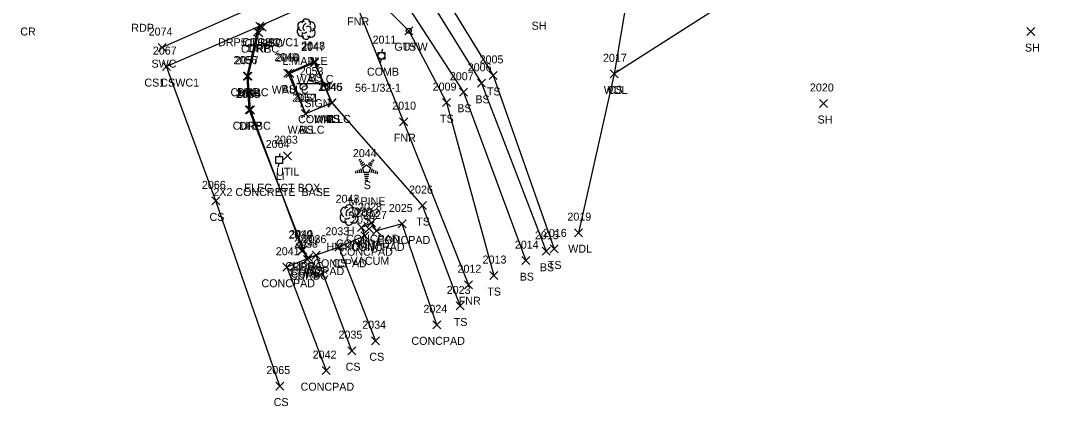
# Model space of a CAD drawing. Extents: x 1477930 to 1480780, y 774090 to 784647.
# Drawn here: x 1478653 to 1478912.6, y 774249.4 to 774345.7 of the extents above; entities that cross this region are included whole.
import ezdxf

# ---------------------------------------------------------------- set-up
doc = ezdxf.new("R2010")
doc.units = 0
for name, color, linetype in [('L_A', 7, 'Continuous'), ('L_C', 7, 'Continuous'), ('L_I', 7, 'Continuous'), ('L_TIC', 7, 'Continuous'), ('LAWA', 7, 'Continuous'), ('LELB', 7, 'Continuous'), ('LFNC', 7, 'Continuous'), ('LS', 7, 'Continuous'), ('LTC', 7, 'Continuous'), ('LTD', 7, 'Continuous'), ('LW', 7, 'Continuous'), ('P_A', 7, 'Continuous'), ('P_I', 7, 'Continuous'), ('P_TIC', 7, 'Continuous'), ('R_A', 7, 'Continuous'), ('R_I', 7, 'Continuous'), ('R_TIC', 7, 'Continuous'), ('RC', 7, 'Continuous'), ('RDP', 7, 'Continuous'), ('RSW', 7, 'Continuous'), ('S_A', 7, 'Continuous'), ('S_C', 7, 'Continuous'), ('S_I', 7, 'Continuous'), ('SSGN', 7, 'Continuous'), ('U_A', 7, 'Continuous'), ('U_C', 7, 'Continuous'), ('U_I', 7, 'Continuous'), ('UDEFAULT', 7, 'Continuous'), ('ULP', 7, 'Continuous'), ('UP', 7, 'Continuous'), ('UPGW', 7, 'Continuous')]:
    doc.layers.add(name, color=color, linetype=linetype)

msp = doc.modelspace()

# ---------------------------------------------------------------- linework, layer by layer
at = {"layer": 'L_TIC'}
for points in [[(1478748.89, 774342.18), (1478750.89, 774344.18)], [(1478750.89, 774342.18), (1478748.89, 774344.18)], [(1478904.33, 774341.96), (1478906.33, 774343.96)], [(1478906.33, 774341.96), (1478904.33, 774343.96)], [(1478688.34, 774333.22), (1478690.34, 774335.22)], [(1478690.34, 774333.22), (1478688.34, 774335.22)], [(1478725.32, 774334.13), (1478727.32, 774336.13)], [(1478727.32, 774334.13), (1478725.32, 774336.13)], [(1478725.36, 774334.46), (1478727.36, 774336.46)], [(1478727.36, 774334.46), (1478725.36, 774336.46)], [(1478718.65, 774331.61), (1478720.65, 774333.61)], [(1478720.65, 774331.61), (1478718.65, 774333.61)], [(1478719.13, 774331.46), (1478721.13, 774333.46)], [(1478721.13, 774331.46), (1478719.13, 774333.46)], [(1478770, 774331.01), (1478772, 774333.01)], [(1478772, 774331.01), (1478770, 774333.01)], [(1478800.18, 774331.41), (1478802.18, 774333.41)], [(1478802.18, 774331.41), (1478800.18, 774333.41)], [(1478800.18, 774331.41), (1478802.18, 774333.41)], [(1478802.18, 774331.41), (1478800.18, 774333.41)], [(1478767.09, 774329.04), (1478769.09, 774331.04)], [(1478769.09, 774329.04), (1478767.09, 774331.04)], [(1478758.29, 774324.22), (1478760.29, 774326.22)], [(1478760.29, 774324.22), (1478758.29, 774326.22)], [(1478762.57, 774326.81), (1478764.57, 774328.81)], [(1478764.57, 774326.81), (1478762.57, 774328.81)], [(1478729.67, 774324.14), (1478731.67, 774326.14)], [(1478731.67, 774324.14), (1478729.67, 774326.14)], [(1478729.67, 774324.14), (1478731.67, 774326.14)], [(1478731.67, 774324.14), (1478729.67, 774326.14)], [(1478729.78, 774324.15), (1478731.78, 774326.15)], [(1478731.78, 774324.15), (1478729.78, 774326.15)], [(1478729.78, 774324.15), (1478731.78, 774326.15)], [(1478731.78, 774324.15), (1478729.78, 774326.15)], [(1478729.78, 774324.15), (1478731.78, 774326.15)], [(1478731.78, 774324.15), (1478729.78, 774326.15)], [(1478852.53, 774324), (1478854.53, 774326)], [(1478854.53, 774324), (1478852.53, 774326)], [(1478723.08, 774321.46), (1478725.08, 774323.46)], [(1478725.08, 774321.46), (1478723.08, 774323.46)], [(1478723.08, 774321.46), (1478725.08, 774323.46)], [(1478725.08, 774321.46), (1478723.08, 774323.46)], [(1478723.09, 774321.43), (1478725.09, 774323.43)], [(1478725.09, 774321.43), (1478723.09, 774323.43)], [(1478723.09, 774321.43), (1478725.09, 774323.43)], [(1478725.09, 774321.43), (1478723.09, 774323.43)], [(1478747.61, 774319.46), (1478749.61, 774321.46)], [(1478749.61, 774319.46), (1478747.61, 774321.46)], [(1478700.65, 774299.67), (1478702.65, 774301.67)], [(1478702.65, 774299.67), (1478700.65, 774301.67)], [(1478752.35, 774298.5), (1478754.35, 774300.5)], [(1478754.35, 774298.5), (1478752.35, 774300.5)], [(1478739.57, 774294.21), (1478741.57, 774296.21)], [(1478741.57, 774294.21), (1478739.57, 774296.21)], [(1478747.24, 774293.9), (1478749.24, 774295.9)], [(1478749.24, 774293.9), (1478747.24, 774295.9)], [(1478737.07, 774293.02), (1478739.07, 774295.02)], [(1478739.07, 774293.02), (1478737.07, 774295.02)], [(1478737.89, 774290.97), (1478739.89, 774292.97)], [(1478739.89, 774290.97), (1478737.89, 774292.97)], [(1478738.95, 774292.7), (1478740.95, 774294.7)], [(1478740.95, 774292.7), (1478738.95, 774294.7)], [(1478740.83, 774292.18), (1478742.83, 774294.18)], [(1478742.83, 774292.18), (1478740.83, 774294.18)], [(1478791.3, 774291.73), (1478793.3, 774293.73)], [(1478793.3, 774291.73), (1478791.3, 774293.73)], [(1478731.39, 774288.09), (1478733.39, 774290.09)], [(1478733.39, 774288.09), (1478731.39, 774290.09)], [(1478731.39, 774288.09), (1478733.39, 774290.09)], [(1478733.39, 774288.09), (1478731.39, 774290.09)], [(1478725.74, 774286.12), (1478727.74, 774288.12)], [(1478727.74, 774286.12), (1478725.74, 774288.12)], [(1478725.74, 774286.12), (1478727.74, 774288.12)], [(1478727.74, 774286.12), (1478725.74, 774288.12)], [(1478783.18, 774287.09), (1478785.18, 774289.09)], [(1478785.18, 774287.09), (1478783.18, 774289.09)], [(1478785.22, 774287.67), (1478787.22, 774289.67)], [(1478787.22, 774287.67), (1478785.22, 774289.67)], [(1478718.43, 774283.09), (1478720.43, 774285.09)], [(1478720.43, 774283.09), (1478718.43, 774285.09)], [(1478778.16, 774284.74), (1478780.16, 774286.74)], [(1478780.16, 774284.74), (1478778.16, 774286.74)], [(1478770.1, 774281.02), (1478772.1, 774283.02)], [(1478772.1, 774281.02), (1478770.1, 774283.02)], [(1478763.83, 774278.72), (1478765.83, 774280.72)], [(1478765.83, 774278.72), (1478763.83, 774280.72)], [(1478761.71, 774273.42), (1478763.71, 774275.42)], [(1478763.71, 774273.42), (1478761.71, 774275.42)], [(1478755.89, 774268.71), (1478757.89, 774270.71)], [(1478757.89, 774268.71), (1478755.89, 774270.71)], [(1478740.6, 774264.73), (1478742.6, 774266.73)], [(1478742.6, 774264.73), (1478740.6, 774266.73)], [(1478734.67, 774262.25), (1478736.67, 774264.25)], [(1478736.67, 774262.25), (1478734.67, 774264.25)], [(1478728.22, 774257.26), (1478730.22, 774259.26)], [(1478730.22, 774257.26), (1478728.22, 774259.26)], [(1478716.68, 774253.41), (1478718.68, 774255.41)], [(1478718.68, 774253.41), (1478716.68, 774255.41)]]:
    msp.add_lwpolyline(points, dxfattribs=at)
at = {"layer": 'LAWA'}
msp.add_lwpolyline([(1479011.38, 774343.55), (1478995.1, 774366.59), (1478968.24, 774384.07), (1478947.58, 774395.67), (1478961.25, 774413.39), (1478952.73, 774420.76), (1478901.61, 774417.12), (1478856.8, 774391.87), (1478808.81, 774377.19), (1478801.18, 774332.41), (1478792.3, 774292.73)], dxfattribs=at)
at = {"layer": 'LELB'}
for points in [[(1478934.45, 774450.58), (1478925.02, 774444.04), (1478895.86, 774426.81), (1478850.02, 774405.81), (1478804.52, 774385.73), (1478757.11, 774369.6), (1478745.11, 774364.76), (1478741.82, 774359.99), (1478746.47, 774354.13), (1478763.57, 774327.81), (1478779.16, 774285.74)], [(1478959.46, 774383.59), (1478932.04, 774383.18), (1478897.67, 774379.29), (1478866.23, 774373.98), (1478801.18, 774332.41)], [(1478757.11, 774369.6), (1478758.28, 774367.33), (1478749.03, 774360.76), (1478768.09, 774330.04), (1478784.18, 774288.09)], [(1478758.28, 774367.33), (1478753.39, 774360.66), (1478771, 774332.01), (1478786.22, 774288.67)], [(1478734.59, 774354.16), (1478739.86, 774353.19), (1478749.89, 774343.18), (1478759.29, 774325.22), (1478771.1, 774282.02)], [(1478717.68, 774254.41), (1478701.65, 774300.67), (1478689.34, 774334.22)], [(1478730.78, 774325.15), (1478726.36, 774335.46), (1478719.65, 774332.61), (1478724.09, 774322.43)], [(1478730.78, 774325.15), (1478724.09, 774322.43)], [(1478762.71, 774274.42), (1478753.35, 774299.5), (1478730.78, 774325.15)], [(1478732.39, 774289.09), (1478741.6, 774265.73)], [(1478735.67, 774263.25), (1478726.74, 774287.12)]]:
    msp.add_lwpolyline(points, dxfattribs=at)
at = {"layer": 'LFNC'}
msp.add_lwpolyline([(1478736.95, 774349.5), (1478748.61, 774320.46), (1478764.83, 774279.72)], dxfattribs=at)
at = {"layer": 'LS'}
msp.add_lwpolyline([(1478756.89, 774269.71), (1478748.24, 774294.9), (1478741.83, 774293.18), (1478740.57, 774295.21), (1478738.07, 774294.02), (1478738.89, 774291.97), (1478732.39, 774289.09), (1478726.74, 774287.12), (1478719.43, 774284.09), (1478729.22, 774258.26)], dxfattribs=at)
at = {"layer": 'LTC'}
for p, q in [((1478737.44, 774310.81), (1478737.8, 774311.07)), ((1478737.65, 774310.35), (1478738.18, 774310.73)), ((1478740.47, 774310.71), (1478741.02, 774310.31)), ((1478740.84, 774311.05), (1478741.26, 774310.75)), ((1478736.48, 774308.09), (1478736.63, 774307.62)), ((1478736.93, 774308.31), (1478737.14, 774307.66)), ((1478737.39, 774308.53), (1478737.66, 774307.69)), ((1478737.84, 774308.74), (1478738.17, 774307.72)), ((1478737.86, 774309.88), (1478738.57, 774310.39)), ((1478738.07, 774309.42), (1478738.95, 774310.05)), ((1478738.3, 774308.96), (1478739.31, 774309.7)), ((1478738.3, 774308.96), (1478738.68, 774307.77)), ((1478739.31, 774309.7), (1478740.3, 774308.97)), ((1478739.73, 774310.01), (1478740.54, 774309.42)), ((1478740.3, 774308.97), (1478739.91, 774307.77)), ((1478740.1, 774310.36), (1478740.78, 774309.86)), ((1478740.74, 774308.7), (1478740.4, 774307.66)), ((1478741.19, 774308.45), (1478740.9, 774307.56)), ((1478741.63, 774308.2), (1478741.39, 774307.47)), ((1478739.91, 774307.77), (1478738.68, 774307.77)), ((1478739.88, 774307.27), (1478738.73, 774307.27)), ((1478739.79, 774306.77), (1478738.8, 774306.77)), ((1478739.71, 774306.27), (1478738.88, 774306.27)), ((1478739.62, 774305.77), (1478738.95, 774305.77)), ((1478742.08, 774307.95), (1478741.89, 774307.37))]:
    msp.add_line(p, q, dxfattribs=at)
at = {"layer": 'LTD'}
for p, q in [((1478724.21, 774343.63), (1478724.21, 774343.63)), ((1478724.21, 774343.63), (1478724.21, 774343.63)), ((1478734.94, 774297.2), (1478734.94, 774297.2)), ((1478734.94, 774297.2), (1478734.94, 774297.2))]:
    msp.add_line(p, q, dxfattribs=at)
for centre in [(1478724.26, 774345.06), (1478734.99, 774298.63)]:
    msp.add_arc(centre, 1.05, 335.5272, 180.9563, dxfattribs=at)
for centre, major_axis, ratio, start_param, end_param in [((1478723.42, 774344.29), (1.21, -0.51), 0.895232, 1.570796, 4.712389), ((1478724.01, 774344.09), (-0.208, -0.792), 0.645439, 3.141593, 6.283185), ((1478724.72, 774343.46), (-0.5, 0.667), 0.989748, 3.141593, 6.283185), ((1478725.26, 774344.21), (-1.14, -0.48), 0.949671, 1.570796, 4.712389), ((1478723.13, 774342.92), (0.58, -1.04), 0.959034, 3.141593, 6.283185), ((1478724.22, 774342.13), (0.26, 1.06), 0.942809, 1.570796, 4.712389), ((1478723.76, 774342.88), (-0.625, -0.083), 0.423636, 0, 3.141593), ((1478725.22, 774342.8), (-1.09, 0.79), 0.841452, 1.570796, 4.712389), ((1478734.15, 774297.87), (1.21, -0.51), 0.895232, 1.570796, 4.712389), ((1478734.74, 774297.66), (-0.208, -0.792), 0.645439, 3.141593, 6.283185), ((1478735.44, 774297.03), (-0.5, 0.667), 0.989748, 3.141593, 6.283185), ((1478735.99, 774297.78), (-1.14, -0.48), 0.949671, 1.570796, 4.712389), ((1478733.86, 774296.49), (0.58, -1.04), 0.959034, 3.141593, 6.283185), ((1478734.94, 774295.7), (0.26, 1.06), 0.942809, 1.570796, 4.712389), ((1478734.49, 774296.45), (-0.625, -0.083), 0.423636, 0, 3.141593), ((1478735.94, 774296.37), (-1.09, 0.79), 0.841452, 1.570796, 4.712389)]:
    msp.add_ellipse(centre, major_axis=major_axis, ratio=ratio, start_param=start_param, end_param=end_param, dxfattribs=at)
at = {"layer": 'LW'}
for points in [[(1478730.67, 774325.14), (1478726.32, 774335.13), (1478720.13, 774332.46), (1478724.08, 774322.46)], [(1478730.67, 774325.14), (1478724.08, 774322.46)]]:
    msp.add_lwpolyline(points, dxfattribs=at)
at = {"layer": 'P_TIC'}
for points in [[(1478722.17, 774287.23), (1478724.17, 774289.23)], [(1478724.17, 774287.23), (1478722.17, 774289.23)]]:
    msp.add_lwpolyline(points, dxfattribs=at)
at = {"layer": 'R_TIC'}
for points in [[(1478711.68, 774343.31), (1478713.68, 774345.31)], [(1478713.68, 774343.31), (1478711.68, 774345.31)], [(1478711.68, 774343.31), (1478713.68, 774345.31)], [(1478713.68, 774343.31), (1478711.68, 774345.31)], [(1478711.68, 774343.31), (1478713.68, 774345.31)], [(1478713.68, 774343.31), (1478711.68, 774345.31)], [(1478712.29, 774343.07), (1478714.29, 774345.07)], [(1478714.29, 774343.07), (1478712.29, 774345.07)], [(1478711.12, 774341.88), (1478713.12, 774343.88)], [(1478713.12, 774341.88), (1478711.12, 774343.88)], [(1478711.39, 774341.69), (1478713.39, 774343.69)], [(1478713.39, 774341.69), (1478711.39, 774343.69)], [(1478687.25, 774337.96), (1478689.25, 774339.96)], [(1478689.25, 774337.96), (1478687.25, 774339.96)], [(1478688.34, 774333.22), (1478690.34, 774335.22)], [(1478690.34, 774333.22), (1478688.34, 774335.22)], [(1478708.48, 774330.85), (1478710.48, 774332.85)], [(1478710.48, 774330.85), (1478708.48, 774332.85)], [(1478708.78, 774330.81), (1478710.78, 774332.81)], [(1478710.78, 774330.81), (1478708.78, 774332.81)], [(1478709.02, 774322.41), (1478711.02, 774324.41)], [(1478711.02, 774322.41), (1478709.02, 774324.41)], [(1478709.32, 774322.45), (1478711.32, 774324.45)], [(1478711.32, 774322.45), (1478709.32, 774324.45)], [(1478722.45, 774287.39), (1478724.45, 774289.39)], [(1478724.45, 774287.39), (1478722.45, 774289.39)], [(1478723.81, 774285.51), (1478725.81, 774287.51)], [(1478725.81, 774285.51), (1478723.81, 774287.51)], [(1478723.59, 774284.99), (1478725.59, 774286.99)], [(1478725.59, 774284.99), (1478723.59, 774286.99)], [(1478723.59, 774284.99), (1478725.59, 774286.99)], [(1478725.59, 774284.99), (1478723.59, 774286.99)]]:
    msp.add_lwpolyline(points, dxfattribs=at)
at = {"layer": 'RC'}
msp.add_lwpolyline([(1478724.81, 774286.51), (1478724.59, 774285.99), (1478723.45, 774288.39), (1478710.32, 774323.45), (1478709.78, 774331.81), (1478712.39, 774342.69), (1478712.68, 774344.31), (1478713.29, 774344.07)], dxfattribs=at)
at = {"layer": 'RDP'}
msp.add_lwpolyline([(1478724.59, 774285.99), (1478710.02, 774323.41), (1478709.48, 774331.85), (1478712.12, 774342.88), (1478712.68, 774344.31)], dxfattribs=at)
at = {"layer": 'RSW'}
for points in [[(1478732.52, 774358.51), (1478715.18, 774350.96), (1478688.25, 774338.96)], [(1478732.52, 774358.51), (1478734.59, 774354.16), (1478712.68, 774344.31), (1478689.34, 774334.22)]]:
    msp.add_lwpolyline(points, dxfattribs=at)
at = {"layer": 'SSGN'}
for p, q in [((1478721.95, 774330), (1478730.55, 774330)), ((1478725.97, 774329.09), (1478725.97, 774329.09))]:
    msp.add_line(p, q, dxfattribs=at)
for centre in [(1478723.61, 774329.16), (1478728.83, 774329.09)]:
    msp.add_circle(centre, 0.833, dxfattribs=at)
at = {"layer": 'UDEFAULT'}
for points in [[(1478718.6, 774310.96), (1478720.6, 774312.96)], [(1478720.6, 774310.96), (1478718.6, 774312.96)]]:
    msp.add_lwpolyline(points, dxfattribs=at)
at = {"layer": 'ULP'}
for p, q in [((1478716.7, 774310.05), (1478716.7, 774311.72)), ((1478716.7, 774311.72), (1478718.36, 774311.72)), ((1478717.7, 774312.55), (1478717.53, 774311.72)), ((1478717.53, 774310.88), (1478717.53, 774310.88)), ((1478718.36, 774311.72), (1478718.36, 774310.05)), ((1478718.36, 774310.05), (1478716.7, 774310.05)), ((1478717.28, 774309.22), (1478717.53, 774310.05))]:
    msp.add_line(p, q, dxfattribs=at)
at = {"layer": 'UP'}
for p, q in [((1478742.22, 774336.11), (1478742.22, 774337.78)), ((1478742.22, 774337.78), (1478743.89, 774337.78)), ((1478743.3, 774338.61), (1478743.05, 774337.78)), ((1478743.05, 774336.94), (1478743.05, 774336.94)), ((1478743.89, 774337.78), (1478743.89, 774336.11)), ((1478743.89, 774336.11), (1478742.22, 774336.11)), ((1478742.8, 774335.28), (1478743.05, 774336.11))]:
    msp.add_line(p, q, dxfattribs=at)
msp.add_circle((1478743.05, 774336.94), 0.833, dxfattribs=at)
at = {"layer": 'UPGW'}
for radius in [0.625, 0.0833]:
    msp.add_circle((1478749.89, 774343.18), radius, dxfattribs=at)

# ---------------------------------------------------------------- texts
at = {"layer": 'L_A'}
for s, p in [('FNR', (1478734.49, 774344.5)), ('SH', (1478780.57, 774343.43)), ('H', (1478723.65, 774338.63)), ('TS', (1478748.3, 774338.18)), ('SH', (1478903.82, 774337.96)), ('WALLC', (1478721.86, 774330.13)), ('BS', (1478724.8, 774330.46)), ('CS', (1478687.78, 774329.22)), ('WALLC', (1478715.66, 774327.46)), ('BS', (1478718.1, 774327.61)), ('TS', (1478769.41, 774327.01)), ('WDL', (1478798.6, 774327.41)), ('CS', (1478799.62, 774327.41)), ('BS', (1478766.53, 774325.04)), ('BS', (1478762.01, 774322.81)), ('WALLC', (1478726.21, 774320.14)), ('WALLC', (1478726.21, 774320.14)), ('TS', (1478729.19, 774320.15)), ('BS', (1478729.22, 774320.15)), ('BS', (1478729.22, 774320.15)), ('TS', (1478757.7, 774320.22)), ('SH', (1478852.02, 774320)), ('WALLC', (1478719.62, 774317.46)), ('WALLC', (1478719.62, 774317.46)), ('BS', (1478722.53, 774317.43)), ('BS', (1478722.53, 774317.43)), ('FNR', (1478746.15, 774315.46)), ('S', (1478738.63, 774303.6)), ('CS', (1478700.1, 774295.67)), ('TS', (1478751.76, 774294.5)), ('H', (1478734.38, 774292.2)), ('CONCPAD', (1478731.71, 774289.02)), ('CONCPAD', (1478734.22, 774290.21)), ('CONCPAD', (1478735.47, 774288.18)), ('MMF', (1478737.24, 774288.7)), ('CONCPAD', (1478741.89, 774289.9)), ('CONCPAD', (1478732.53, 774286.97)), ('WDL', (1478789.72, 774287.73)), ('CONCPAD', (1478726.03, 774284.09)), ('CS', (1478730.83, 774284.09)), ('BS', (1478782.62, 774283.09)), ('TS', (1478784.63, 774283.67)), ('CONCPAD', (1478720.39, 774282.12)), ('CS', (1478725.18, 774282.12)), ('BS', (1478777.6, 774280.74)), ('CONCPAD', (1478713.08, 774279.09)), ('TS', (1478769.51, 774277.02)), ('FNR', (1478762.37, 774274.72)), ('TS', (1478761.12, 774269.42)), ('CONCPAD', (1478750.54, 774264.71)), ('CS', (1478740.04, 774260.73)), ('CS', (1478734.11, 774258.25)), ('CONCPAD', (1478722.86, 774253.26)), ('CS', (1478716.13, 774249.41))]:
    msp.add_text(s, height=2, dxfattribs=at).set_placement(p)
at = {"layer": 'L_C'}
for s, p in [('L.MAPLE', (1478718.33, 774334.63)), ('M.PINE', (1478734.85, 774299.6)), ('HICKORY', (1478729.32, 774288.2)), ('VACUM', (1478735.35, 774284.7))]:
    msp.add_text(s, height=2, dxfattribs=at).set_placement(p)
at = {"layer": 'L_I'}
for s, p in [('2067', (1478685.95, 774337.22)), ('2047', (1478722.99, 774338.13)), ('2048', (1478723.02, 774338.46)), ('2049', (1478716.31, 774335.61)), ('2050', (1478716.7, 774335.46)), ('2005', (1478767.58, 774335.01)), ('2017', (1478798.41, 774335.41)), ('2017', (1478798.41, 774335.41)), ('2006', (1478764.62, 774333.04)), ('2007', (1478760.15, 774330.81)), ('2046', (1478727.28, 774328.14)), ('2046', (1478727.28, 774328.14)), ('2045', (1478727.44, 774328.15)), ('2045', (1478727.44, 774328.15)), ('2045', (1478727.44, 774328.15)), ('2009', (1478755.86, 774328.22)), ('2020', (1478850.11, 774328)), ('2052', (1478720.75, 774325.43)), ('2052', (1478720.75, 774325.43)), ('2051', (1478721.31, 774325.46)), ('2051', (1478721.31, 774325.46)), ('2010', (1478745.75, 774323.46)), ('2044', (1478735.91, 774311.6)), ('2066', (1478698.21, 774303.67)), ('2026', (1478749.96, 774302.5)), ('2043', (1478731.61, 774300.2)), ('2029', (1478734.72, 774297.02)), ('2032', (1478736.61, 774296.7)), ('2028', (1478737.23, 774298.21)), ('2027', (1478738.49, 774296.18)), ('2025', (1478744.91, 774297.9)), ('2019', (1478789.52, 774295.73)), ('2030', (1478735.46, 774294.97)), ('2033', (1478729.05, 774292.09)), ('2033', (1478729.05, 774292.09)), ('2015', (1478781.41, 774291.09)), ('2016', (1478783.39, 774291.67)), ('2036', (1478723.35, 774290.12)), ('2036', (1478723.35, 774290.12)), ('2014', (1478776.39, 774288.74)), ('2041', (1478716.66, 774287.09)), ('2012', (1478762.06, 774282.72)), ('2013', (1478768.33, 774285.02)), ('2023', (1478759.37, 774277.42)), ('2024', (1478753.55, 774272.71)), ('2034', (1478738.26, 774268.73)), ('2035', (1478732.33, 774266.25)), ('2042', (1478725.88, 774261.26)), ('2065', (1478714.3, 774257.41))]:
    msp.add_text(s, height=2, dxfattribs=at).set_placement(p)
at = {"layer": 'LTC'}
msp.add_text('.', height=1.04, rotation=270, dxfattribs=at).set_placement((1478739.19, 774308.71))
at = {"layer": 'P_A'}
for s, p in [('RDP', (1478680.56, 774342.91)), ('CR', (1478652.82, 774341.99)), ('RDP', (1478720.66, 774283.23))]:
    msp.add_text(s, height=2, dxfattribs=at).set_placement(p)
at = {"layer": 'P_I'}
msp.add_text('2039', height=2, dxfattribs=at).set_placement((1478719.82, 774291.23))
at = {"layer": 'R_A'}
for s, p in [('DRP5 CC SWC1', (1478702.25, 774339.31)), ('CURBC', (1478707.97, 774337.69)), ('CURBC', (1478708.26, 774339.31)), ('CURBC', (1478708.87, 774339.07)), ('DRP', (1478709.61, 774337.88)), ('DRP', (1478710.16, 774339.31)), ('SWC', (1478685.61, 774333.96)), ('CS1 SWC1', (1478683.83, 774329.22)), ('CURBC', (1478705.36, 774326.81)), ('DRP', (1478706.97, 774326.85)), ('CURBC', (1478705.9, 774318.45)), ('DRP', (1478707.51, 774318.41)), ('CURBC', (1478719.03, 774283.39)), ('CURBC', (1478720.17, 774280.99)), ('CURBC', (1478720.39, 774281.51)), ('DRP', (1478722.08, 774280.99))]:
    msp.add_text(s, height=2, dxfattribs=at).set_placement(p)
at = {"layer": 'R_I'}
for s, p in [('2074', (1478684.91, 774341.96)), ('2067', (1478685.95, 774337.22)), ('2056', (1478706.09, 774334.85)), ('2057', (1478706.44, 774334.81)), ('2055', (1478706.68, 774326.41)), ('2054', (1478706.98, 774326.45)), ('2040', (1478720.02, 774291.39)), ('2038', (1478721.25, 774288.99)), ('2038', (1478721.25, 774288.99)), ('2037', (1478721.47, 774289.51))]:
    msp.add_text(s, height=2, dxfattribs=at).set_placement(p)
at = {"layer": 'S_A'}
msp.add_text('TSIGN', height=2, dxfattribs=at).set_placement((1478722.15, 774324.08))
at = {"layer": 'S_C'}
msp.add_text('COMM', height=2, dxfattribs=at).set_placement((1478722.24, 774320.08))
at = {"layer": 'S_I'}
msp.add_text('2053', height=2, dxfattribs=at).set_placement((1478722.63, 774332.08))
at = {"layer": 'U_A'}
for s, p in [('GUYW', (1478746.29, 774338.18)), ('COMB', (1478739.44, 774331.94)), ('UTIL', (1478716.76, 774306.96)), ('LI', (1478716.63, 774305.88))]:
    msp.add_text(s, height=2, dxfattribs=at).set_placement(p)
at = {"layer": 'U_C'}
for s, p in [('56-1/32-1', (1478736.47, 774327.94)), ('2X2 CONCRETE  BASE', (1478701.07, 774301.88)), ('ELEC JCT BOX', (1478708.75, 774302.96))]:
    msp.add_text(s, height=2, dxfattribs=at).set_placement(p)
at = {"layer": 'U_I'}
for s, p in [('2011', (1478740.85, 774339.94)), ('2064', (1478714.14, 774313.88)), ('2063', (1478716.21, 774314.96))]:
    msp.add_text(s, height=2, dxfattribs=at).set_placement(p)

doc.saveas('drawing.dxf')
